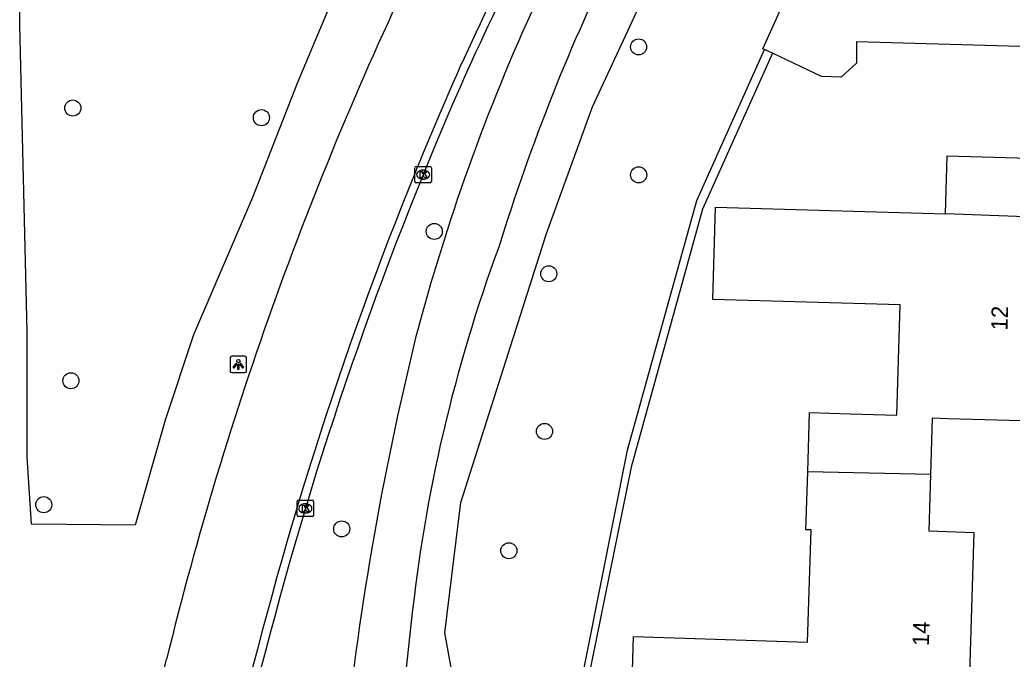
# Model space of a CAD drawing. Extents: x 162082 to 163393, y 388091 to 388632.
# Drawn here: x 162126.8 to 162187.2, y 388206.7 to 388245.6 of the extents above; entities that cross this region are included whole.
import ezdxf

# ---------------------------------------------------------------- set-up
doc = ezdxf.new("R2010")
doc.units = 0
for name, color, linetype in [('IMGEO_Berm_groen', 7, 'Continuous'), ('IMGEO_Boom', 7, 'Continuous'), ('IMGEO_Fietspad_gesloten', 7, 'Continuous'), ('IMGEO_Kolk', 7, 'Continuous'), ('IMGEO_Lichtpunt', 7, 'Continuous'), ('IMGEO_Muur', 7, 'Continuous'), ('IMGEO_Pand', 7, 'Continuous'), ('IMGEO_Pand_nummerreeks', 7, 'Continuous'), ('IMGEO_Rijbaan_lokaal_open', 7, 'Continuous'), ('IMGEO_Rijbaan_regionaal_gesloten', 7, 'Continuous')]:
    doc.layers.add(name, color=color, linetype=linetype)

msp = doc.modelspace()

# ---------------------------------------------------------------- linework, layer by layer
at = {"layer": 'IMGEO_Berm_groen'}
for points in [[(162193.018, 388311.476), (162180.686, 388299.296), (162174.794, 388292.565), (162164.913, 388279.995), (162159.416, 388272.159), (162154.453, 388264.185), (162150.758, 388257.597), (162147.107, 388250), (162143.664, 388241.768), (162140.921, 388234.763), (162137.33, 388226.41), (162135.613, 388221.211), (162133.771, 388214.818), (162127.473, 388214.895), (162127.211, 388218.972), (162127.21, 388226.62), (162126.756, 388245.293), (162126.809, 388250), (162126.865, 388255.1), (162127.17, 388261.503), (162131.88, 388276.058), (162143.113, 388299.11), (162147.83, 388309.193)], [(162155.641, 388169.499), (162149.29, 388170.484), (162151.506, 388186.435), (162153.504, 388199.591), (162153.36, 388204.265), (162152.635, 388208.277), (162153.616, 388216.204), (162158.829, 388232.574), (162161.634, 388240.291), (162165.112, 388247.818), (162166.315, 388250), (162169.541, 388255.855), (162173.82, 388263.104), (162179.303, 388271.066), (162185.601, 388278.37), (162195.833, 388289.739), (162193.849, 388291.667)]]:
    msp.add_lwpolyline(points, dxfattribs=at)
at = {"layer": 'IMGEO_Boom'}
for centre in [(162164.436, 388243.94), (162129.982, 388240.22), (162141.465, 388239.632), (162164.44, 388236.151), (162151.994, 388232.706), (162158.966, 388230.129), (162129.864, 388223.617), (162158.707, 388220.536), (162128.212, 388216.074), (162146.356, 388214.601), (162156.535, 388213.27)]:
    msp.add_circle(centre, 0.489, dxfattribs=at)
at = {"layer": 'IMGEO_Fietspad_gesloten'}
msp.add_lwpolyline([(162150.596, 388208.951), (162146.281, 388169.197)], dxfattribs=at)
for centre, radius, start, end in [((162272.303, 388195.984), 121.751, 153.66232, 162.91897), ((162273.166, 388193.916), 126.504, 155.33064, 165.20021), ((162244.129, 388199.115), 94.049, 159.69961, 173.99707), ((162328.02, 388182.653), 182.442, 166.18059, 174.3349)]:
    msp.add_arc(centre, radius, start, end, dxfattribs=at)
at = {"layer": 'IMGEO_Kolk'}
for p, q in [((162150.815, 388235.737), (162150.815, 388236.589)), ((162150.89, 388236.663), (162151.742, 388236.663)), ((162151.303, 388236.443), (162151.328, 388236.443)), ((162151.816, 388236.589), (162151.816, 388235.737)), ((162151.742, 388235.663), (162150.89, 388235.663)), ((162151.326, 388235.883), (162151.301, 388235.883)), ((162143.643, 388215.422), (162143.643, 388216.274)), ((162143.718, 388216.348), (162144.57, 388216.348)), ((162144.131, 388216.128), (162144.156, 388216.128)), ((162144.644, 388216.274), (162144.644, 388215.422)), ((162144.154, 388215.568), (162144.129, 388215.568)), ((162144.57, 388215.348), (162143.718, 388215.348))]:
    msp.add_line(p, q, dxfattribs=at)
for points in [[(162150.815, 388235.737), (162150.815, 388236.589)], [(162150.89, 388236.663), (162151.742, 388236.663)], [(162151.136, 388236.363), (162151.259, 388236.363), (162151.259, 388236.212), (162151.389, 388236.363), (162151.553, 388236.363), (162151.407, 388236.212), (162151.56, 388235.963), (162151.408, 388235.963), (162151.323, 388236.127), (162151.259, 388236.06), (162151.259, 388235.963), (162151.136, 388235.963), (162151.136, 388236.363)], [(162151.816, 388236.589), (162151.816, 388235.737)], [(162151.742, 388235.663), (162150.89, 388235.663)], [(162143.643, 388215.422), (162143.643, 388216.274)], [(162143.718, 388216.348), (162144.57, 388216.348)], [(162144.644, 388216.274), (162144.644, 388215.422)], [(162143.964, 388216.048), (162144.087, 388216.048), (162144.087, 388215.897), (162144.217, 388216.048), (162144.381, 388216.048), (162144.235, 388215.897), (162144.388, 388215.648), (162144.236, 388215.648), (162144.151, 388215.812), (162144.087, 388215.745), (162144.087, 388215.648), (162143.964, 388215.648), (162143.964, 388216.048)], [(162144.57, 388215.348), (162143.718, 388215.348)]]:
    msp.add_lwpolyline(points, dxfattribs=at)
for centre, start, end in [((162150.892, 388236.587), 91.55205, 178.44795), ((162150.892, 388236.587), 91.55205, 178.44795), ((162151.74, 388236.587), 1.55205, 88.44795), ((162151.74, 388236.587), 1.55205, 88.44795), ((162150.892, 388235.739), 181.55205, 268.44795), ((162150.892, 388235.739), 181.55205, 268.44795), ((162151.74, 388235.739), 271.55205, 358.44795), ((162151.74, 388235.739), 271.55205, 358.44795), ((162143.72, 388216.272), 91.55205, 178.44795), ((162143.72, 388216.272), 91.55205, 178.44795), ((162144.568, 388216.272), 1.55205, 88.44795), ((162144.568, 388216.272), 1.55205, 88.44795), ((162143.72, 388215.424), 181.55205, 268.44795), ((162143.72, 388215.424), 181.55205, 268.44795), ((162144.568, 388215.424), 271.55205, 358.44795), ((162144.568, 388215.424), 271.55205, 358.44795)]:
    msp.add_arc(centre, 0.0765, start, end, dxfattribs=at)
for centre, major_axis, ratio, start_param, end_param in [((162151.302, 388236.163), (-0.387, 0.002), 0.722429, 4.712389, 7.853982), ((162151.327, 388236.163), (-0.39, 0.002), 0.717154, 1.570796, 4.712389), ((162144.13, 388215.848), (-0.387, 0.002), 0.722429, 4.712389, 7.853982), ((162144.155, 388215.848), (-0.39, 0.002), 0.717154, 1.570796, 4.712389)]:
    msp.add_ellipse(centre, major_axis=major_axis, ratio=ratio, start_param=start_param, end_param=end_param, dxfattribs=at)
at = {"layer": 'IMGEO_Lichtpunt'}
for p, q in [((162139.565, 388225.016), (162139.565, 388224.209)), ((162139.565, 388225.016), (162139.565, 388224.209)), ((162140.467, 388225.111), (162139.659, 388225.111)), ((162140.467, 388225.111), (162139.659, 388225.111)), ((162140.561, 388224.209), (162140.561, 388225.016)), ((162140.561, 388224.209), (162140.561, 388225.016)), ((162139.659, 388224.115), (162140.467, 388224.115)), ((162139.659, 388224.115), (162140.467, 388224.115))]:
    msp.add_line(p, q, dxfattribs=at)
for points in [[(162139.939, 388224.68), (162139.978, 388224.652), (162139.79, 388224.39), (162139.752, 388224.417), (162139.939, 388224.68)], [(162140.041, 388224.632), (162140.088, 388224.632), (162140.088, 388224.31), (162140.041, 388224.31), (162140.041, 388224.632)], [(162140.151, 388224.652), (162140.189, 388224.679), (162140.376, 388224.417), (162140.337, 388224.389), (162140.151, 388224.652)]]:
    msp.add_lwpolyline(points, dxfattribs=at)
msp.add_circle((162140.064, 388224.814), 0.0994, dxfattribs=at)
for centre, start, end in [((162139.659, 388225.016), 90, 180), ((162139.659, 388225.016), 90, 180), ((162140.467, 388225.016), 0, 90), ((162140.467, 388225.016), 0, 90), ((162139.659, 388224.209), 180, 270), ((162139.659, 388224.209), 180, 270), ((162140.467, 388224.209), 270, 0), ((162140.467, 388224.209), 270, 360)]:
    msp.add_arc(centre, 0.0946, start, end, dxfattribs=at)
at = {"layer": 'IMGEO_Muur'}
for points in [[(162155.641, 388169.499), (162157.762, 388186.972), (162160.453, 388202.779), (162163.757, 388219.4), (162167.977, 388234.595), (162172.103, 388243.782)], [(162172.591, 388243.552), (162168.323, 388234.056), (162163.98, 388218.368), (162160.807, 388202.671), (162158.079, 388186.902), (162155.992, 388168.648)]]:
    msp.add_lwpolyline(points, dxfattribs=at)
at = {"layer": 'IMGEO_Pand'}
for points in [[(162172.103, 388243.782), (162172.009, 388243.827), (162174.687, 388249.789), (162174.799, 388249.786)], [(162183.13, 388233.787), (162183.23, 388237.319), (162188.906, 388237.157), (162189.099, 388243.93), (162177.701, 388244.255), (162177.707, 388242.955), (162176.763, 388242.099), (162175.572, 388242.141), (162172.591, 388243.552)], [(162172.591, 388243.552), (162172.103, 388243.782)], [(162174.733, 388218.078), (162174.847, 388221.689), (162177.326, 388221.61), (162180.165, 388221.52), (162180.356, 388228.234), (162168.964, 388228.559), (162169.125, 388234.186), (162183.13, 388233.787)], [(162189.615, 388233.54), (162183.13, 388233.787)], [(162189.261, 388221.138), (162183.262, 388221.309), (162182.319, 388221.336), (162182.211, 388217.911)], [(162163.96, 388202.542), (162164.135, 388208.05), (162174.724, 388207.714), (162174.94, 388214.538), (162174.621, 388214.548), (162174.733, 388218.078)], [(162182.211, 388217.911), (162174.733, 388218.078)], [(162182.211, 388217.911), (162182.102, 388214.475), (162184.853, 388214.387), (162184.456, 388201.851), (162182.005, 388201.929)]]:
    msp.add_lwpolyline(points, dxfattribs=at)
at = {"layer": 'IMGEO_Rijbaan_lokaal_open'}
for centre, radius, start, end in [((162312.5, 388170.811), 173.945, 152.91894, 156.02641), ((162363.419, 388149.87), 228.985, 156.41525, 165.51142), ((162278.165, 388169.399), 141.578, 164.53166, 170.5084)]:
    msp.add_arc(centre, radius, start, end, dxfattribs=at)
at = {"layer": 'IMGEO_Rijbaan_regionaal_gesloten'}
msp.add_lwpolyline([(162128.163, 388167.313), (162128.953, 388173.214), (162134.063, 388199.663), (162135.696, 388206.672)], dxfattribs=at)
for centre, radius, start, end in [((162347.23, 388154.825), 217.795, 154.08767, 166.22816), ((162311.152, 388171.471), 172.945, 152.99495, 156.04573), ((162363.429, 388149.867), 229.496, 156.41562, 165.51059), ((162276.156, 388169.841), 140.023, 164.48887, 170.54592)]:
    msp.add_arc(centre, radius, start, end, dxfattribs=at)

# ---------------------------------------------------------------- texts
at = {"layer": 'IMGEO_Pand_nummerreeks'}
for s, rotation, p in [('12', 88.36501, (162186.898, 388226.673)), ('14', 88.18393, (162182.112, 388207.464))]:
    msp.add_text(s, height=1, rotation=rotation, dxfattribs=at).set_placement(p)

doc.saveas('drawing.dxf')
